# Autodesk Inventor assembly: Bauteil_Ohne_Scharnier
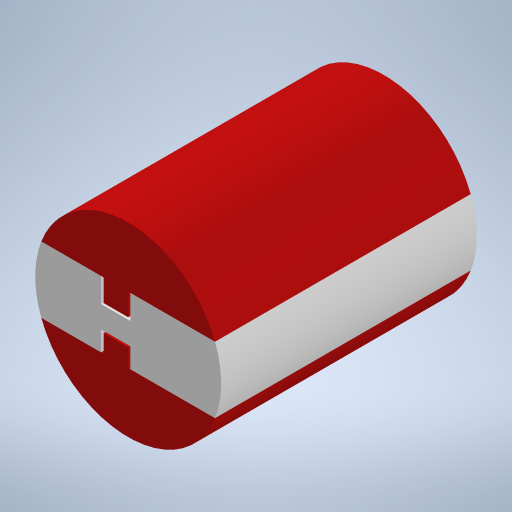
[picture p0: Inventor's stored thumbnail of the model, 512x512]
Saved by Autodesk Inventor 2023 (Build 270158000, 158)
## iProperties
Created: 2025-02
Part Number: Bauteil_Ohne_Scharnier
Document SubType Name: Assembly
Designer: MVM1
Author: MVM1
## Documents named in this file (4)
- Z:\Projektname\Bauteile\Muster_Forum\Bauteil_Ohne_Scharnier.iam
- Z:\Projektname\Bauteile\Muster_Forum\Neuer Ordner\Klemplate_1.ipt
- Z:\Projektname\Bauteile\Muster_Forum\Neuer Ordner\Klemplatte_2.ipt
- Z:\Projektname\Bauteile\Muster_Forum\Neuer Ordner\Mittelteil.ipt
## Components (3 placed, 3 different names)
1. Klemplate_1:1
2. Klemplatte_2:1
3. Mittelteil:1
